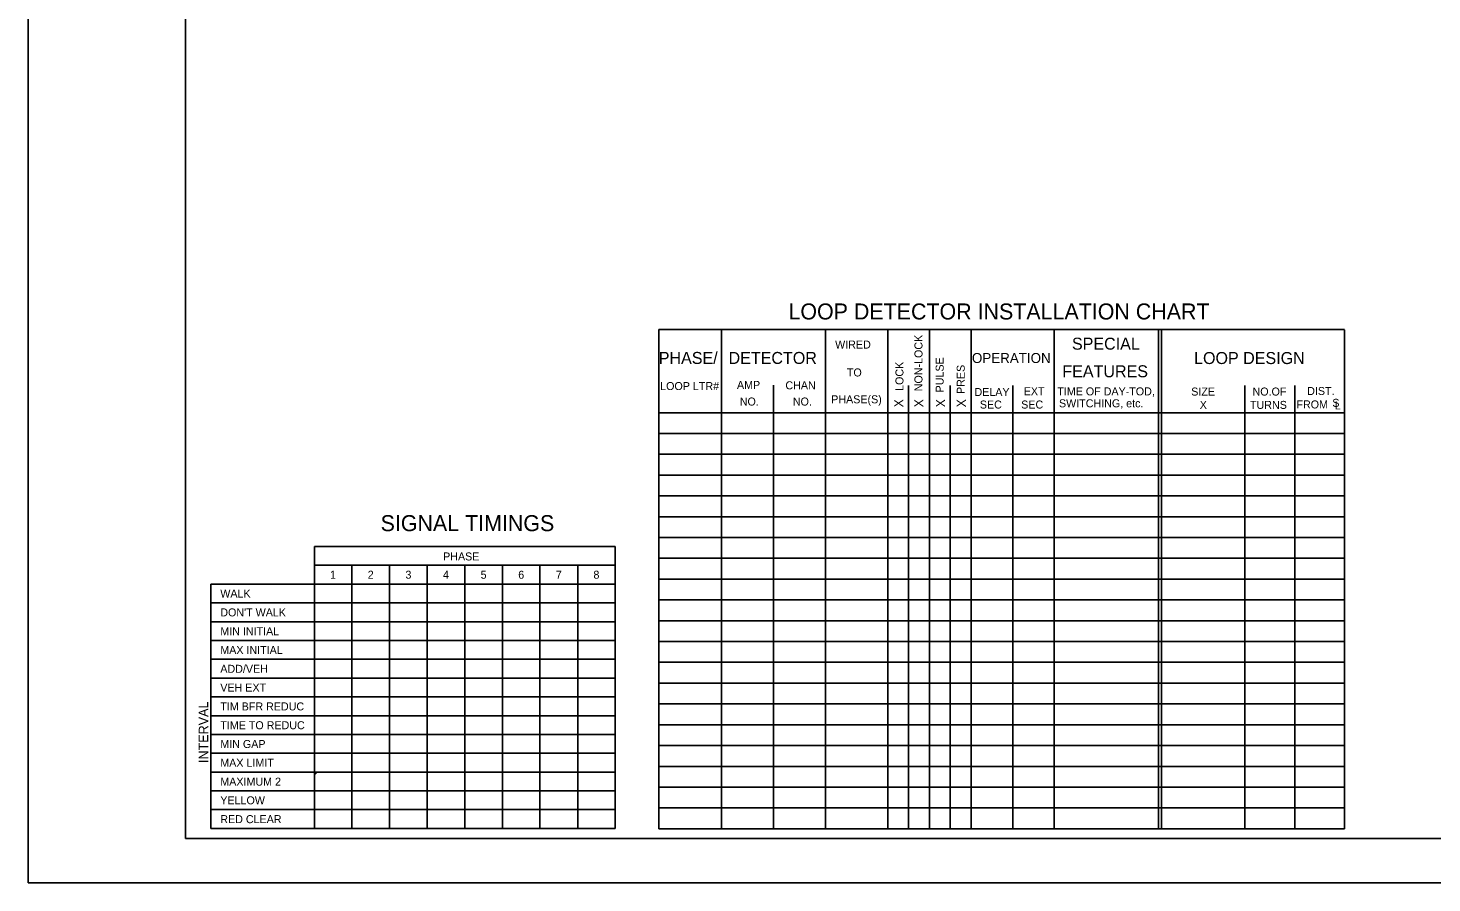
# Model space of a CAD drawing. Extents: x 0 to 3.01, y -0.05 to 1.83.
# Drawn here: x 0 to 1.504, y 0 to 0.917 of the extents above; entities that cross this region are included whole.
import ezdxf

# ---------------------------------------------------------------- set-up
doc = ezdxf.new("R2010")
doc.units = 0
for name, color, linetype in [('RD_SHT_IplotShp', 7, 'Continuous'), ('TR_TS_Border', 7, 'Continuous'), ('TR_TS_Loop Detector Chart', 7, 'Continuous'), ('TR_TS_Phase1', 7, 'Continuous'), ('TR_TS_Phase2', 7, 'Continuous'), ('TR_TS_Phase3', 7, 'Continuous'), ('TR_TS_Phase4', 7, 'Continuous'), ('TR_TS_Phase5', 7, 'Continuous'), ('TR_TS_Phase6', 7, 'Continuous'), ('TR_TS_Phase7', 7, 'Continuous'), ('TR_TS_Phase8', 7, 'Continuous')]:
    doc.layers.add(name, color=color, linetype=linetype)

msp = doc.modelspace()

# ---------------------------------------------------------------- linework, layer by layer
at = {"layer": 'RD_SHT_IplotShp'}
msp.add_lwpolyline([(0, 0), (3, 0), (3, 1.8333), (0, 1.8333)], close=True, dxfattribs=at)
at = {"layer": 'TR_TS_Border'}
for p, q in [((0, 0), (0, 1.8333)), ((0.1686, 1.7754), (0.1686, 0.0475)), ((0.3068, 0.3607), (0.6293, 0.3607)), ((0.3068, 0.3607), (0.3068, 0.3204)), ((0.6293, 0.3607), (0.6293, 0.0585)), ((0.3068, 0.3406), (0.6293, 0.3406)), ((0.3471, 0.3406), (0.3471, 0.0585)), ((0.3874, 0.3406), (0.3874, 0.0585)), ((0.4278, 0.3406), (0.4278, 0.0585)), ((0.4681, 0.3406), (0.4681, 0.0585)), ((0.5083, 0.3406), (0.5083, 0.0585)), ((0.5486, 0.3406), (0.5486, 0.0585)), ((0.589, 0.3406), (0.589, 0.0585)), ((0.1959, 0.3204), (0.1959, 0.0585)), ((0.1959, 0.3204), (0.3068, 0.3204)), ((0.3068, 0.3204), (0.3068, 0.1189)), ((0.3068, 0.3204), (0.6293, 0.3204)), ((0.1959, 0.3003), (0.6293, 0.3003)), ((0.1959, 0.2801), (0.6293, 0.2801)), ((0.1959, 0.26), (0.6293, 0.26)), ((0.1959, 0.2398), (0.6293, 0.2398)), ((0.1959, 0.2197), (0.6293, 0.2197)), ((0.1959, 0.1995), (0.6293, 0.1995)), ((0.1959, 0.1793), (0.6293, 0.1793)), ((0.1959, 0.1592), (0.6293, 0.1592)), ((0.1959, 0.139), (0.6293, 0.139)), ((0.1959, 0.1189), (0.3068, 0.1189)), ((0.3068, 0.0585), (0.3068, 0.1189)), ((0.3068, 0.1189), (0.6293, 0.1189)), ((0.3068, 0.116), (0.3099, 0.1189)), ((0.1959, 0.0987), (0.6293, 0.0987)), ((0.1959, 0.0786), (0.6293, 0.0786)), ((0.1686, 0.0475), (2.9623, 0.0475)), ((0.1959, 0.0585), (0.6293, 0.0585)), ((0.0238, 0), (3, 0))]:
    msp.add_line(p, q, dxfattribs=at)
at = {"layer": 'TR_TS_Loop Detector Chart'}
for p, q in [((0.6761, 0.5934), (1.4109, 0.5934)), ((0.6761, 0.0581), (0.6761, 0.5934)), ((0.743, 0.0581), (0.743, 0.5934)), ((0.8545, 0.0581), (0.8545, 0.5934)), ((0.9214, 0.0581), (0.9214, 0.5935)), ((0.966, 0.0581), (0.966, 0.5932)), ((1.0106, 0.0581), (1.0106, 0.5934)), ((1.0998, 0.0581), (1.0998, 0.5932)), ((1.2113, 0.0581), (1.2113, 0.5932)), ((1.2147, 0.0581), (1.2147, 0.5931)), ((1.4109, 0.5932), (1.4109, 0.0581)), ((0.7988, 0.0581), (0.7988, 0.5336)), ((0.9437, 0.0581), (0.9437, 0.5334)), ((0.9883, 0.0581), (0.9883, 0.5334)), ((1.0552, 0.0581), (1.0552, 0.5334)), ((1.3039, 0.0581), (1.3039, 0.5334)), ((1.3574, 0.0581), (1.3574, 0.5334)), ((0.6761, 0.5042), (1.4109, 0.5042)), ((0.6761, 0.4819), (1.4109, 0.4819)), ((0.6761, 0.4596), (1.4109, 0.4596)), ((0.6761, 0.4373), (1.4109, 0.4373)), ((0.6761, 0.415), (1.4109, 0.415)), ((0.6761, 0.3927), (1.4109, 0.3927)), ((0.6761, 0.3704), (1.4109, 0.3704)), ((0.6761, 0.3481), (1.4109, 0.3481)), ((0.6761, 0.3258), (1.4109, 0.3258)), ((0.6761, 0.3035), (1.4109, 0.3035)), ((0.6761, 0.2812), (1.4109, 0.2812)), ((0.6761, 0.2589), (1.4109, 0.2589)), ((0.6761, 0.2366), (1.4109, 0.2366)), ((0.6761, 0.2143), (1.4109, 0.2143)), ((0.6761, 0.192), (1.4109, 0.192)), ((0.6761, 0.1697), (1.4109, 0.1697)), ((0.6761, 0.1473), (1.4109, 0.1473)), ((0.6761, 0.125), (1.4109, 0.125)), ((0.6761, 0.1027), (1.4109, 0.1027)), ((0.6761, 0.0804), (1.4109, 0.0804)), ((0.6761, 0.0581), (1.4109, 0.0581))]:
    msp.add_line(p, q, dxfattribs=at)

# ---------------------------------------------------------------- texts
at = {"layer": 'TR_TS_Border'}
for s, height, p in [('SIGNAL TIMINGS', 0.017156, (0.3778, 0.3772)), ('MAX INITIAL', 0.008578, (0.206, 0.2455))]:
    msp.add_text(s, height=height, dxfattribs=at).set_placement(p)
for s, height, rotation, p in [('PHASE', 0.00858, 360, (0.4448, 0.3458)), ('WALK', 0.00858, 360, (0.206, 0.306)), ("DON'T WALK", 0.00858, 360, (0.206, 0.2858)), ('MIN INITIAL', 0.008578, 360, (0.206, 0.2656)), ('ADD/VEH', 0.00858, 360, (0.206, 0.2253)), ('VEH EXT', 0.00858, 360, (0.206, 0.2052)), ('INTERVAL', 0.01008, 90, (0.193, 0.1286)), ('TIM BFR REDUC', 0.008578, 360, (0.206, 0.185)), ('TIME TO REDUC', 0.008578, 360, (0.206, 0.1648)), ('MIN GAP', 0.00858, 360, (0.206, 0.1447)), ('MAX LIMIT', 0.00858, 360, (0.206, 0.1245)), ('MAXIMUM 2', 0.00858, 360, (0.206, 0.1043)), ('YELLOW', 0.00858, 360, (0.206, 0.0843)), ('RED CLEAR', 0.00858, 360, (0.206, 0.0641))]:
    msp.add_text(s, height=height, rotation=rotation, dxfattribs=at).set_placement(p)
at = {"layer": 'TR_TS_Loop Detector Chart'}
for s, height, p in [('LOOP DETECTOR INSTALLATION CHART', 0.017156, (0.8149, 0.6042)), ('WIRED', 0.00858, (0.8649, 0.573)), ('SPECIAL', 0.01287, (1.1187, 0.5718)), ('PHASE/', 0.01287, (0.6759, 0.5565)), ('DETECTOR', 0.01287, (0.7507, 0.5565)), ('OPERATION', 0.01072, (1.0115, 0.5575)), ('LOOP DESIGN', 0.012867, (1.2496, 0.5564)), ('TO', 0.00858, (0.8775, 0.5431)), ('FEATURES', 0.01287, (1.1084, 0.5422)), ('LOOP LTR#', 0.00858, (0.6774, 0.5285)), ('AMP', 0.00858, (0.7597, 0.5297)), ('CHAN', 0.00858, (0.8116, 0.5293)), ('DELAY', 0.00858, (1.0142, 0.5221)), ('EXT', 0.00858, (1.067, 0.523)), ('TIME OF DAY-TOD,', 0.008578, (1.103, 0.5228)), ('SIZE', 0.00858, (1.2465, 0.5226)), ('NO.OF', 0.00858, (1.3122, 0.5226)), ('DIST.', 0.00858, (1.3708, 0.5232)), ('NO.', 0.00858, (0.7627, 0.5119)), ('NO.', 0.00858, (0.8196, 0.5119)), ('PHASE(S)', 0.00858, (0.8607, 0.5143)), ('SEC', 0.00858, (1.02, 0.5087)), ('SEC', 0.00858, (1.0643, 0.5087)), ('SWITCHING, etc.', 0.008578, (1.1048, 0.51)), ('   X   ', 0.00858, (1.2461, 0.5083)), ('TURNS', 0.00858, (1.3095, 0.5083)), ('FROM', 0.00858, (1.3593, 0.5088)), ('S', 0.00858, (1.3977, 0.5105)), ('L', 0.00858, (1.4004, 0.5077))]:
    msp.add_text(s, height=height, dxfattribs=at).set_placement(p)
for s, height, p in [('NON-LOCK', 0.00858, (0.9585, 0.5272)), ('LOCK', 0.00858, (0.9381, 0.5276)), (' PULSE', 0.00858, (0.9812, 0.5228)), ('PRES', 0.00858, (1.0038, 0.5243)), ('X', 0.00972, (0.9379, 0.51)), ('X', 0.00981, (0.9595, 0.51)), ('X', 0.00981, (0.9828, 0.51)), ('X', 0.00981, (1.005, 0.51))]:
    msp.add_text(s, height=height, rotation=90, dxfattribs=at).set_placement(p)
at = {"layer": 'TR_TS_Phase1'}
msp.add_text('1', height=0.00858, rotation=360, dxfattribs=at).set_placement((0.3236, 0.3262))
at = {"layer": 'TR_TS_Phase2'}
msp.add_text('2', height=0.00858, rotation=360, dxfattribs=at).set_placement((0.364, 0.3262))
at = {"layer": 'TR_TS_Phase3'}
msp.add_text('3', height=0.00858, rotation=360, dxfattribs=at).set_placement((0.4044, 0.3262))
at = {"layer": 'TR_TS_Phase4'}
msp.add_text('4', height=0.00858, rotation=360, dxfattribs=at).set_placement((0.4446, 0.3262))
at = {"layer": 'TR_TS_Phase5'}
msp.add_text('5', height=0.00858, rotation=360, dxfattribs=at).set_placement((0.485, 0.3262))
at = {"layer": 'TR_TS_Phase6'}
msp.add_text('6', height=0.00858, rotation=360, dxfattribs=at).set_placement((0.5253, 0.3262))
at = {"layer": 'TR_TS_Phase7'}
msp.add_text('7', height=0.00858, rotation=360, dxfattribs=at).set_placement((0.5656, 0.3262))
at = {"layer": 'TR_TS_Phase8'}
msp.add_text('8', height=0.00858, rotation=360, dxfattribs=at).set_placement((0.6059, 0.3262))

doc.saveas('drawing.dxf')
